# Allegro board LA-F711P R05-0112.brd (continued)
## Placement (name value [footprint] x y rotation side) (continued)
PR404  4.7_0603_5%  [R_0603]  143.05 58.51 90 bottom
PR405  0_0402_5%  [R_0402]  152.73 55.91 90 top
PR414  0_0402_5%  [R0402_0OHM]  149.78 63.98 270 bottom
PR415  0_0402_5%  [R_0402]  134.84 60.73 0 top
PR416  0_0402_5%  [R_0402]  150.67 63.07 90 bottom
PR417  10K_0402_1%  [R_0402]  155.19 63.97 180 bottom
PR418  10K_0402_1%  [R_0402]  155.27 62.86 270 bottom
PR419  10K_0402_1%  [R_0402]  153.36 63.12 90 bottom
PR420  10K_0402_1%  [R_0402]  156.2 61.93 90 bottom
PR425  0_0402_5%  [R_0402]  151.85 55.91 90 top
PR427  200K_0402_1%  [R_0402]  151.62 64.01 270 bottom
PR501  20K_0402_1%  [R_0402]  121.49 8.92 180 bottom
PR502  4.7_0603_5%  [R_0603]  127.18 3.99 90 bottom
PR504  0_0402_5%  [R0402_0OHM]  124.38 8.86 270 top
PR505  1M_0402_1%  [R_0402]  123.36 7.95 90 top
PR506  10K_0402_1%  [R_0402]  119.64 7.78 90 bottom
PR509  1M_0402_1%  [R_0402]  152.89 126.53 270 top
PR510  10.2K_0402_1%  [R_0402]  146.03 126.15 270 top
PR511  0_0402_5%  [R0402_0OHM]  154.68 126.52 180 top
PR512  5.1K_0402_1%  [R_0402]  145.14 127.99 270 top
PR513  0_0402_5%  [R0402_0OHM]  67.99 5.57 90 bottom
PR514  1M_0402_1%  [R_0402]  68.93 6.38 270 bottom
PR515  21.5K_0402_1%  [R_0402]  75.74 7.63 270 bottom
PR516  10.2K_0402_1%  [R_0402]  76.55 5.87 180 bottom
PR517  100K_0402_5%  [R_0402]  118.41 9.04 180 bottom
PR607  0_0402_5%  [R_0402]  165.01 10.18 0 bottom
PR609  0_0402_5%  [R_0402]  165.93 9.32 180 bottom
PR901  0.01_1206_1%  [R_1206_4P-D]  10.38 55.54 0 top
PR909  2_0603_1%  [R_0603]  11.45 53.92 270 top
PR910  2_0603_1%  [R_0603]  12.67 53.91 270 top
PR914  3.3_0603_1%  [R_0603]  13.91 33.78 0 bottom
PR915  4.7_0603_5%  [R_0603]  11.69 31.34 0 bottom
PR916  1_0805_5%~D  [R_0805]  11.79 38.04 90 bottom
PR917  0.005_1206_1%  [R_1206_4P-D]  27.35 4.41 180 top
PR918  100K_0402_1%  [R_0402]  9.95 39.47 270 top
PR919  0_0402_5%  [R_0402]  9.06 39.47 270 bottom
PR920  0_0402_5%  [R0402_0OHM]  9.06 39.47 270 top
PR921  4.7_0603_5%  [R_0603]  10.7 29.43 270 top
PR922  0_0402_5%  [R0402_0OHM]  8.17 39.47 270 bottom
PR923  4.7_1206_5%  [R_1206]  15.63 23.62 180 top
PR924  4.7_1206_5%  [R_1206]  15.53 14.97 180 top
PR925  154K_0402_1%  [R_0402]  7.16 40.79 180 bottom
PR926  0_0402_5%  [R0402_0OHM]  8.17 39.47 270 top
PR927  1M_0402_1%  [R_0402]  7.6 44.67 0 bottom
PR928  0_0402_5%  [R0402_0OHM]  7.29 39.47 270 top
PR929  0_0402_5%  [R0402_0OHM]  8.28 29.43 270 top
PR930  100K_0402_1%  [R_0402]  5.89 40.72 90 top
PR931  100K_0402_1%  [R_0402]  7.16 41.63 270 top
PR932  105K_0402_1%  [R_0402]  4.36 38.68 90 top
PR933  100K_0402_1%  [R_0402]  5.38 39.47 270 top
PR934  0_0402_5%  [R_0402]  6.35 35.4 90 bottom
PR935  0_0402_5%  [R0402_0OHM]  4.49 38.56 90 bottom
PR936  0_0402_5%  [R0402_0OHM]  5.44 33.98 90 top
PR937  1_0603_1%  [R_0603]  7.97 28.57 270 bottom
PR938  1_0603_1%  [R_0603]  6.74 28.56 270 bottom
PR939  0_0402_5%  [R0402_0OHM]  5.51 48.11 270 top
PR940  100_0402_1%  [R_0402]  5.76 31.95 90 bottom
PR941  0_0402_5%  [R0402_0OHM]  6.4 48.11 270 top
PR942  0_0402_5%  [R0402_0OHM]  8.1 45.36 0 top
PR943  0_0603_5%  [R_0603]  13.87 36.54 0 bottom
PR944  442K_0402_1%  [R_0402]  15.37 36.54 180 top
PR945  100K_0402_5%  [R_0402]  10.44 36.41 270 bottom
PR946  0_0402_5%  [R0402_0OHM]  14.61 45.93 0 top
PR947  0_0402_5%  [R0402_0OHM]  5.38 38.56 90 bottom
PR948  10.2K_0402_1%  [R_0402]  5.44 32.99 270 top
PR949  0_0402_5%  [R0402_0OHM]  6.22 33.81 180 bottom
PR950  0_0402_5%  [R_0402]  10 48.92 0 top
PR951  0_0402_5%  [R0402_0OHM]  4.49 41.76 270 top
PR953  100K_0402_1%  [R_0402]  15.63 45.06 270 top
PR960  0_0402_5%  [R0402_0OHM]  9.06 36.52 90 bottom
PR1201  240K_0402_1%  [R_0402]  49.15 101.62 180 bottom
PR1202  300K_0402_5%  [R_0402]  51.35 120.6 90 top
PR1203  1.8M_0402_1%  [R_0402]  46.13 104.74 0 bottom
PR1205  499K_0402_1%  [R_0402]  42.32 113.39 270 top
PR1206  1K_0402_1%  [R_0402]  49.15 105.41 180 bottom
PR1207  499K_0402_1%  [R_0402]  49.58 120.6 90 top
PR1208  102K_0402_1%  [R_0402]  49.15 104.52 180 bottom
PR1209  100K_0402_5%  [R_0402]  70.74 102.35 180 top
PR1210  1M_0402_5%  [R_0402]  60.52 100.82 180 top
PR1211  0_0402_5%  [R0402_0OHM]  60.52 101.83 180 top
PR1212  49.9K_0402_1%  [R_0402]  41.94 111.34 180 top
PR1213  49.9K_0402_1%  [R_0402]  50.54 122.58 180 top
PR1214  100K_0402_5%  [R_0402]  65.87 102.76 90 top
PR1215  0_0402_5%  [R0402_0OHM]  60.5 102.86 180 top
PR1216  0_0402_5%  [R0402_0OHM]  57.3 103.73 180 top
PR1217  84.5K_0402_1%  [R_0402]  48.23 102.51 0 bottom
PR1218  0_0402_5%  [R0402_0OHM]  65.97 105.3 0 top
PR1219  23.2K_0402_1%  [R_0402]  48.31 100.69 270 bottom
PR1220  0_0402_5%  [R0402_0OHM]  57.03 107.76 90 top
PR1221  0_0402_5%  [R_0402]  68.7 107.97 180 top
PR1222  100K_0402_5%  [R_0402]  58.09 108.68 270 top
PR1223  0_0402_5%  [R0402_0OHM]  70.06 104.11 270 top
PR1224  100K_0402_5%  [R_0402]  69.57 107.97 0 top
PR1225  0_0402_5%  [R_0402]  64.91 104.69 270 top
PR1226  100K_0402_5%  [R_0402]  63.29 105.99 90 top
PR1227  100K_0402_5%  [R_0402]  23.54 124.28 90 bottom
PR1228  499K_0402_1%  [R_0402]  26.82 121.48 270 bottom
PR1229  49.9K_0402_1%  [R_0402]  26.27 102.12 90 bottom
PR1230  100K_0402_5%  [R_0402]  70.15 107.04 270 bottom
PR1231  100K_0402_5%  [R_0402]  79.98 113.18 0 bottom
PR1232  100K_0402_5%  [R_0402]  68.83 105.05 180 bottom
PR1233  100K_0402_5%  [R_0402]  82.8 113.44 180 bottom
PR1234  100K_0402_5%  [R_0402]  66.01 109.24 0 bottom
PR1235  100K_0402_5%  [R_0402]  83.69 110.26 180 bottom
PR1236  100K_0402_5%  [R_0402]  29.13 105.38 270 bottom
PR1237  100K_0402_1%  [R_0402]  38.87 99.84 0 bottom
PR1238  0_0402_5%  [R0402_0OHM]  43.84 106.64 180 bottom
PR1239  150K_0402_1%  [R_0402]  41.58 98.63 90 bottom
PR1240  100K_0402_1%  [R_0402]  39.39 106.8 270 bottom
PR1241  0_0402_5%  [R0402_0OHM]  71.12 108.99 180 bottom
PR1242  0_0402_5%  [R0402_0OHM]  87.88 113.31 180 bottom
PR1243  0_0402_5%  [R0402_0OHM]  40.42 106.8 270 bottom
PR1244  0_0402_5%  [R0402_0OHM]  63.29 107.01 90 bottom
PR1245  0_0402_5%  [R0402_0OHM]  76.5 112.22 90 bottom
PR1246  100K_0402_1%  [R_0402]  43.48 99.54 270 bottom
PR1247  100K_0402_1%  [R_0402]  39.78 101.69 180 bottom
PR1248  0_0402_5%  [R_0402]  47.4 97.47 90 bottom
PR1249  10K_0402_5%  [R_0402]  49.25 97.47 90 bottom
PR1250  0_0402_5%  [R0402_0OHM]  48.29 97.47 90 bottom
PR1251  300K_0402_5%  [R_0402]  40.43 105.1 90 top
PR1252  100K_0402_5%  [R_0402]  40.43 107.01 90 top
PR1253  100K_0402_5%  [R_0402]  64.75 102.79 270 top
PR1254  0_0402_5%  [R_0402]  61.48 105.85 0 top
PR1255  150K_0402_1%  [R_0402]  28.24 121.39 270 top
PR1257  0_0402_5%  [R0402_0OHM]  85.59 110.26 180 bottom
PR1258  0_0402_5%  [R_0402]  71.12 108.1 180 bottom
PR1259  100K_0402_5%  [R_0402]  65.02 105.18 0 bottom
PR1260  0_0402_5%  [R_0402]  62.33 109.24 0 bottom
PR1261  0_0402_5%  [R_0402]  64.11 109.24 0 bottom
PR1262  100K_0402_5%  [R_0402]  58.14 103.73 0 top
PR1700  100_0402_1%  [R_0402]  109.81 84.37 0 bottom
PR1701  12K_0402_1%  [R_0402]  63.95 80.59 180 top
PR1702  7.5K_0603_1%  [R_0603]  65.95 84.45 0 bottom
PR1703  10_0402_1%  [R_0402]  65.7 82.34 180 top
PR1704  499_0402_1%  [R_0402]  65.13 76.58 180 top
PR1705  100_0402_1%  [R_0402]  64.78 77.95 0 top
PR1706  45.3_0402_1%  [R_0402]  65.7 78.82 180 top
PR1707  45.3_0402_1%  [R_0402]  65.69 79.71 180 top
PR1708  0_0402_5%  [R0402_0OHM]  65.68 85.01 180 top
PR1709  1K_0402_1%  [R_0402]  63.92 85.87 180 top
PR1710  0_0402_5%  [R0402_0OHM]  65.68 85.88 90 top
PR1711  1.74K_0402_1%  [R_0402]  63.93 87.65 270 top
PR1712  100_0402_1%  [R_0402]  60.91 77.37 0 top
PR1713  28K_0402_1%  [R_0402]  60.12 82.69 0 bottom
PR1714  100_0402_1%  [R_0402]  112.49 84.37 180 bottom
PR1715  49.9_0402_1%  [R_0402]  62.64 79.7 0 top
PR1716  10K_0402_1%  [R_0402]  63.93 81.91 180 bottom
PR1717  0_0402_5%  [R0402_0OHM]  63.56 78.81 180 top
PR1718  12K_0402_1%  [R_0402]  60.68 85.37 0 bottom
PR1719  10_0402_1%  [R_0402]  62.64 77.93 0 top
PR1720  1.5K_0402_1%  [R_0402]  67.28 83.24 180 top
PR1721  100_0402_1%  [R_0402]  103.45 84.98 270 bottom
PR1722  38.3K +-1% 0402  [R_0402]  61.03 80.92 180 bottom
PR1723  0_0402_5%  [R0402_0OHM]  61.86 89.26 270 bottom
PR1724  0_0402_5%  [R0402_0OHM]  63.01 81 0 bottom
PR1725  100_0402_1%  [R_0402]  98.13 82.94 180 bottom
PR1726  0_0402_5%  [R0402_0OHM]  61.27 90.99 270 top
PR1727  1.78K_0402_1%  [R_0402]  61.28 89.26 270 top
PR1728  0_0402_5%  [R0402_0OHM]  60.98 76.5 0 top
PR1729  100_0402_1%  [R_0402]  103.53 82.89 180 bottom
PR1730  2.05K_0402_1%  [R_0402]  61.01 74.72 0 top
PR1731  49.9_0402_1%  [R_0402]  59.51 89.25 90 top
PR1732  26.1K_0402_1%  [R_0402]  58.01 84.56 90 bottom
PR1733  30.1K_0402_1%  [R_0402]  57.72 78.68 90 bottom
PR1734  1K_0402_1%  [R_0402]  59.47 88.39 0 top
PR1735  0_0402_5%  [R0402_0OHM]  62.78 74.75 270 top
PR1736  100_0402_1%  [R_0402]  99.03 82.92 90 bottom
PR1737  3.65K_0402_1%  [R_0402]  57.76 89.23 90 top
PR1738  49.9_0402_1%  [R_0402]  59.53 73.06 270 top
PR1739  1K_0402_1%  [R_0402]  58.64 73.93 0 top
PR1740  3.65K_0402_1%  [R_0402]  57.77 73.08 270 top
PR1741  30.1K_0402_1%  [R_0402]  56.87 89.28 270 top
PR1742  13K_0402_1%  [R_0402]  56.03 76.94 270 top
PR1743  75K_0402_1%  [R_0402]  56.01 90.14 180 top
PR1744  75K_0402_1%  [R_0402]  56.04 74.02 180 top
PR1745  1K_0402_1%  [R_0402]  54.28 77.83 90 bottom
PR1746  165K_0402_1%  [R_0402]  55.15 91.55 0 top
PR1747  113K_0603_1%  [R_0603]  58.4 91.97 180 top
PR1748  165K_0402_1%  [R_0402]  54.28 74.04 90 top
PR1749  76.8K_0603_1%  [R_0603]  53.11 73.23 270 top
PR1750  113K_0603_1%  [R_0603]  58.4 93.24 180 top
PR1751  113K_0603_1%  [R_0603]  58.4 94.51 180 top
PR1752  113K_0603_1%  [R_0603]  58.4 95.78 180 top
PR1753  1K_0402_1%  [R_0402]  51.08 85.24 0 top
PR1754  2.2_0603_5%  [R_0603]  50.57 82.42 0 top
PR1755  11.8K_0402_1%  [R_0402]  54.24 79.61 0 bottom
PR1756  25.5K_0402_1%  [R_0402]  54.3 81.33 0 bottom
PR1757  7.68K_0402_1%  [R_0402]  58.16 91.34 180 bottom
PR1758  102K +-1% 0402  [R_0402]  53.67 83.11 0 bottom
PR1759  4.3K +-1% 0402  [R_0402]  53.67 82.22 0 bottom
PR1760  24.9K_0402_1%  [R_0402]  51.54 81.35 180 top
PR1761  97.6K_0402_1%  [R_0402]  51.54 80.08 180 top
PR1762  97.6K_0402_1%  [R_0402]  51.54 79.19 180 top
PR1763  7.68K_0402_1%  [R_0402]  51.99 72.92 270 top
PR1764  7.68K_0402_1%  [R_0402]  58.16 92.35 180 bottom
PR1765  7.68K_0402_1%  [R_0402]  58.16 93.37 180 bottom
PR1766  7.68K_0402_1%  [R_0402]  58.16 94.39 180 bottom
PR1767  0_0402_5%  [R0402_0OHM]  77.27 94.63 90 top
PR1768  0_0402_5%  [R0402_0OHM]  50.59 69.32 270 bottom
PR1769  8.66K +-1% 0402  [R_0402]  77.27 96.38 90 top
PR1770  8.66K +-1% 0402  [R_0402]  48.81 68.4 90 bottom
PR1771  2.21K +-1% 0402  [R_0402]  63.95 88.54 180 top
PR1772  1K_0402_1%  [R_0402]  54.91 86.05 90 bottom
PR1773  1K_0402_1%  [R_0402]  53.89 86.05 90 bottom
PR1774  1K_0402_1%  [R_0402]  52.88 86.05 90 bottom
PR1775  1K_0402_1%  [R_0402]  51.86 86.05 90 bottom
PR1776  1K_0402_1%  [R_0402]  53.34 76.1 180 top
PR1800  2_0603_5%  [R_0603]  65.87 98.17 90 top
PR1801  3.9_0603_1%  [R_0603]  70.29 101.69 90 bottom
PR1802  10_0402_1%  [R_0402]  76.88 89.08 90 top
PR1803  1_1206_5%  [R_1206]  73.71 91.85 180 top
PR1804  2_0603_5%  [R_0603]  77.16 100.56 90 top
PR1805  3.9_0603_1%  [R_0603]  79.18 102.43 90 top
PR1806  10_0402_1%  [R_0402]  87.25 92.99 180 top
PR1807  1_1206_5%  [R_1206]  80.77 93.19 90 top
PR1900  2_0603_5%  [R_0603]  85.9 94.08 90 top
PR1901  3.9_0603_1%  [R_0603]  86.05 98.74 180 top
PR1902  10_0402_1%  [R_0402]  91.91 89.05 90 top
PR1903  1_1206_5%  [R_1206]  89.89 93.52 0 top
PR1904  2_0603_5%  [R_0603]  96.16 96.16 180 top
PR1905  3.9_0603_1%  [R_0603]  94.22 99 0 top
PR1906  10_0402_1%  [R_0402]  97.72 89.07 90 top
PR1907  1_1206_5%  [R_1206]  98.32 94.54 180 top
PR2000  2_0603_5%  [R_0603]  43.84 60.33 180 bottom
PR2001  3.9_0603_1%  [R_0603]  42.29 65.14 180 bottom
PR2002  10_0402_1%  [R_0402]  55.11 68.34 180 bottom
PR2003  1_1206_5%  [R_1206]  50.03 59.01 180 bottom
PR2004  2_0603_5%  [R_0603]  104.15 87.03 90 bottom
PR2005  3.9_0603_1%  [R_0603]  104.4 91.89 180 bottom
PR2006  1_1206_5%  [R_1206]  115.61 96.6 180 bottom
PR2007  1K_0402_1%  [R_0402]  50.97 86.07 90 bottom
PR2008  1K_0402_1%  [R_0402]  167 9.65 0 bottom
PR2009  0_0402_5%  [R_0402]  150.02 58.06 0 top
PR2010  0_0402_5%  [R_0402]  154.68 125.63 180 top
PR2011  0_0402_5%  [R_0402]  160.13 8.33 90 bottom
PR2012  0_0402_5%  [R_0402]  161.02 8.33 90 bottom
PR2013  100K_0402_5%  [R_0402]  161.91 9.25 270 bottom
PRP1  100_0804_8P4R_5%  [RP_0804_8P4R]  7.09 12.59 0 top
PT1  PAD~D  [TPC12]  47.29 99.3 180 bottom
PU1  MC74VHC1G08DFT2G SC70 5P AND  [TC7SH08FU_SSOP5]  75.29 116.14 90 top
PU2  AP2204R-3.3TRG1_SOT89-3  [AP2204R-3P3TRG1_SOT89-3]  71.42 113.54 270 bottom
PU100  -  [SY8288BRAC_QFN20_3X3]  88.91 5.61 90 bottom
PU102  -  [SY8288CRAC_QFN20_3X3]  125.37 131.34 180 top
PU200  -  [SY8210AQVC_QFN19_4X3]  44.71 8.83 270 bottom
PU301  -  [SY8286RAC_QFN20_3X3]  169.15 4.9 90 bottom
PU401  -  [SY8057BQDC_QFN16_3X3]  149.93 59.03 0 bottom
PU501  -  [RT8097ALGE_SOT23-6]  122.6 6.49 270 bottom
PU502  -  [EM1109V-AD_DFN3308-8_3X3]  147.43 127.94 270 top
PU503  -  [EM1109V-AD_DFN3308-8_3X3]  74.25 7.75 270 bottom
PU901  ISL9538HRTZTS277_TQFN32_4X4~D  [ISL9538HRTZTS277_TQFN32_4X4]  8.41 31.71 90 top
PU903  MC74VHC1G08DFT2G SC70 5P AND  [TC7SH08FU_SSOP5]  11.53 47.3 270 top
PU1200  MC74VHC1G08DFT2G SC70 5P AND  [TC7SH08FU_SSOP5]  58.57 101.44 90 top
PU1201  -  [LM393DGKR_VSSOP8]  46.38 103.09 180 bottom
PU1700  NCP81215DPA0MNTXG_QFN52_6X6  [NCP81215MNTXG_QFN52_6X6]  59.73 85.47 270 top
PU1800  -  [NCP302045MNTXG_PQFN33_5X5]  68.21 100.47 0 bottom
PU1801  -  [NCP302045MNTXG_PQFN33_5X5]  77.68 100.65 0 bottom
PU1900  NCP302045MN_PQFN33_5X5  [NCP302045MNTXG_PQFN33_5X5]  86.12 96.67 90 bottom
PU1901  NCP302045MN_PQFN33_5X5  [NCP302045MNTXG_PQFN33_5X5]  95.76 96.78 90 bottom
PU2000  NCP302045MN_PQFN33_5X5  [NCP302045MNTXG_PQFN33_5X5]  43.55 62.7 90 bottom
PU2001  NCP302045MN_PQFN33_5X5  [NCP302045MNTXG_PQFN33_5X5]  105.77 89.47 90 bottom
QE2  -  [DMN65D8LDW-7_SOT363-6]  303.18 45.05 0 top
QE3  LMBT3904WT1G SC70-3  [MMBT3904WT1G_SC70-3]  94.13 67.02 180 top
QE4  LMBT3904WT1G SC70-3  [MMBT3904WT1G_SC70-3]  323.12 14.31 90 top
QE5  LMBT3904WT1G SC70-3  [MMBT3904WT1G_SC70-3]  11.48 104.6 90 bottom
QE6  LMBT3904WT1G SC70-3  [MMBT3904WT1G_SC70-3]  99.73 102.28 180 bottom
QE7  LMBT3904WT1G SC70-3  [MMBT3904WT1G_SC70-3]  78.31 10.83 90 bottom
QE11  -  [L2N7002WT1G_SC-70-3]  324.39 17.11 270 top
QE12  -  [L2N7002WT1G_SC-70-3]  318.84 49.55 0 top
QE15  -  [LP2301ALT1G_SOT23-3]  310.94 53.87 0 top
QE17  -  [L2N7002WT1G_SC-70-3]  314.84 51.48 180 top
QH4  -  [DMN65D8LDW-7_SOT363-6]  218.24 9.33 90 top
QH6  -  [L2N7002WT1G_SC-70-3]  196.82 6.12 270 bottom
QH7  -  [LP2301ALT1G_SOT23-3]  202.28 7.92 0 bottom
QL1  -  [DMN65D8LDW-7_SOT363-6]  310.29 87.34 0 top
QL2  -  [DMN65D8LDW-7_SOT363-6]  311.81 92.04 90 top
QN1  -  [DMN65D8LDW-7_SOT363-6]  268.89 16.6 180 bottom
QN6  -  [L2N7002WT1G_SC-70-3]  268.57 10.32 0 top
QR1  -  [L2N7002WT1G_SC-70-3]  37.44 71.47 90 bottom
QT1  -  [DMN66D0LDW-7_SOT363-6]  18.7 83.02 0 top
QV1  -  [AO6405_TSOP6]  123.22 113.76 0 top
QV2  -  [L2N7002WT1G_SC-70-3]  124.62 109.18 90 top
QV3  -  [DMN65D8LDW-7_SOT363-6]  115.05 124.75 270 top
QV4  -  [L2N7002WT1G_SC-70-3]  97.9 122.2 270 top
QV5  -  [L2N7002WT1G_SC-70-3]  119.43 125.31 0 top
QV7  -  [L2N7002WT1G_SC-70-3]  127.22 96.48 90 top
QV8  -  [LP2301ALT1G_SOT23-3]  127.92 102.35 180 top
QV18  -  [MMBT3906H_SOT23-3]  147.36 95.6 180 bottom
QV19  MMBT3904WT1G SC70-3  [MMBT3904WT1G_SC70-3]  152.9 96.56 270 bottom
QV20  -  [MMBT3906H_SOT23-3]  150.68 91.78 180 bottom
QV21  MMBT3904WT1G SC70-3  [MMBT3904WT1G_SC70-3]  157.71 93.05 270 bottom
QZ1  -  [LP2301ALT1G_SOT23-3]  121.16 99.91 90 bottom
QZ2  -  [DMN65D8LDW-7_SOT363-6]  307.26 60.48 0 bottom
QZ3  -  [DDTA144VCA-7-F_SOT23-3]  304.34 58.57 180 bottom
QZ4  -  [L2N7002WT1G_SC-70-3]  301.29 48.41 0 top
QZ7  -  [DMN65D8LDW-7_SOT363-6]  351.64 112.05 270 bottom
QZ15  -  [BSS138W-7-F_SOT323-3]  283.26 2.82 90 top
QZ16  -  [LP2301ALT1G_SOT23-3]  277.4 3 270 top
QZ17  -  [DMN65D8LDW-7_SOT363-6]  297.82 44.51 270 bottom
QZ18  -  [DMN65D8LDW-7_SOT363-6]  291.65 43.96 0 bottom
R274  0_0603_5%  [R0603_0OHM]  16.8 61.44 180 top
RA3  0_0603_5%  [R_0603]  337.47 44.94 90 top
RA5  2.2K_0402_5%  [R_0402]  345.95 35.99 0 bottom
RA6  2.2K_0402_5%  [R_0402]  345.95 37.9 0 bottom
RA7  16.2_0402_1%  [R_0402]  349.26 42.53 0 top
RA8  16.2_0402_1%  [R_0402]  349.22 41.55 0 top
RA9  33_0402_5%  [R_0402]  342.4 30.46 90 top
RA12  1K_0402_5%  [R_0402]  346.2 33.43 180 bottom
RA13  1K_0402_5%  [R_0402]  351.39 38.18 45 top
RA14  22_0402_5%  [R_0402]  340.18 30.46 90 top
RA17  33_0402_5%  [R_0402]  341.32 31.37 270 top
RA18  10K_0402_5%  [R_0402]  337.23 27.28 270 top
RA35  0_0402_5%  [R_0402]  338.34 38.99 270 bottom
RA36  0_0402_5%  [R_0402]  366.98 37.89 90 top
RA37  0_0402_5%  [R_0402]  360.22 23.6 270 top
RA44  100K_0402_5%  [R_0402]  342.85 43.73 90 bottom
RA45  10K_0402_5%  [R_0402]  352.02 37.55 45 top
RA48  0_0402_5%  [R_0402]  335.89 29.87 0 top
RA50  0_0402_5%  [R_0402]  336.34 26.36 90 top
RA51  10K_0402_5%  [R_0402]  353.93 35.64 45 top
RA52  100K_0402_5%  [R_0402]  339.23 30.46 90 top
RA53  0_0402_5%  [R_0402]  350.69 39.14 45 top
RA54  0_0402_5%  [R_0402]  349.93 39.78 45 top
RA57  4.7K_0402_5%  [R_0402]  341.45 43.79 90 top
RA58  4.7K_0402_5%  [R_0402]  342.47 43.79 90 top
RA59  100K_0402_1%  [R_0402]  345.28 32.16 0 top
RA60  200K_0402_1%  [R_0402]  347.19 32.16 0 top
RA61  100K_0402_5%  [R_0402]  345.28 33.17 0 top
RC1  24.9_0402_1%  [R_0402]  120.37 83.59 0 top
RC2  24.9_0402_1%  [R_0402]  122.81 47.01 180 top
RC5  121_0402_1%  [R_0402]  122.81 46.13 180 top
RC6  75_0402_1%  [R_0402]  121.66 47.9 180 top
RC7  100_0402_1%  [R_0402]  121.66 48.79 180 top
RC66  20_0402_5%  [R_0402]  125 87.72 0 bottom
RC71  1K_0402_5%  [R_0402]  138.21 57.49 0 top
RC74  10K_0402_5%  [R_0402]  223.91 36.73 0 bottom
RC75  10K_0402_5%  [R_0402]  219.55 17.28 270 top
RC78  60.4_0402_1%  [R_0402]  139.09 56.61 180 top
RC79  49.9_0402_1%  [R_0402]  71.88 72.1 0 bottom
RC80  1K_0402_5%  [R_0402]  122.84 86.07 180 top
RC83  1K_0402_5%  [R_0402]  71.88 73.09 0 bottom
RC84  499_0402_1%  [R_0402]  73.67 72.57 0 bottom
RC114  49.9_0402_1%  [R_0402]  74.93 66.57 180 bottom
RC115  2.2K_0402_5%  [R_0402]  41.94 48.15 90 top
RC121  1K_0402_5%  [R_0402]  36.61 35.96 90 top
RC122  0_0402_5%  [R_0402]  32.67 36.87 270 top
RC124  1K_0402_5%  [R_0402]  38.91 35.51 90 top
RC126  1K_0402_5%  [R_0402]  43.74 35.58 90 top
RC127  1K_0402_5%  [R_0402]  51.67 54.25 90 top
RC128  1K_0402_5%  [R_0402]  229.54 12.98 0 bottom
RC129  0_0402_5%  [R_0402]  55.11 45.62 180 top
RC132  150_0402_5%  [R_0402]  54.91 48.87 270 top
RC133  1.5K_0402_5%  [R_0402]  55.11 46.51 180 top
RC135  51_0402_5%  [R_0402]  46.51 48.1 90 top
RC136  51_0402_5%  [R_0402]  48.56 48.16 90 top
RC137  3K_0402_5%  [R_0402]  43.84 48.15 90 top
RC138  51_0402_5%  [R_0402]  33.68 35.96 90 top
RC139  51_0402_5%  [R_0402]  74.93 69.75 180 bottom
RC140  100_0402_1%  [R_0402]  100.75 84.72 270 bottom
RC141  100_0402_1%  [R_0402]  100.85 82.96 180 bottom
RC143  0_0402_5%  [R_0402]  73.02 69.87 180 bottom
RC144  0_0402_5%  [R_0402]  42.83 48.15 90 top
RC152  56.2_0402_1%  [R_0402]  69.36 85.93 0 top
RC153  220_0402_5%  [R_0402]  71.18 85.94 0 top
RC157  100_0402_5%  [R_0402]  69.34 85.04 0 top
RC166  1K_0402_5%  [R_0402]  71.04 70.84 270 bottom
RC168  20_0402_5%  [R_0402]  73.86 73.8 90 bottom
RC169  0_0402_5%  [R_0402]  120.17 85.56 270 top
RC171  0_0402_5%  [R_0402]  77.25 48.04 180 top
RC177  30_0402_5%  [R_0402]  115.02 68.29 0 top
RC178  0_0402_5%  [R_0402]  132.18 76.91 0 top
RC179  0_0402_5%  [R_0402]  124.06 83.98 90 top
RC181  1K_0402_5%  [R_0402]  75 69.99 180 top
RC216  0_0603_1%  [R0603_0OHM]  38.64 48.22 0 top
RC217  0_0402_5%  [R_0402]  53.89 48.87 270 top
RC218  150_0402_5%  [R_0402]  53.89 51.28 270 top
RC219  10K_0402_5%  [R_0402]  54.91 51.28 270 top
RC221  49.9_0402_1%  [R_0402]  101.71 82.99 90 bottom
RC228  0_0402_5%  [R_0402]  50.59 48.16 90 top
RC229  0_0402_5%  [R_0402]  49.58 48.16 90 top
RC230  0_0402_5%  [R_0402]  47.4 48.1 90 top
RC239  0_0402_5%  [R_0402]  74.93 68.6 180 bottom
RC240  0_0402_5%  [R_0402]  74.93 67.59 180 bottom
RC241  1.5K_0402_5%  [R_0402]  52.75 51.28 270 top
RC304  0_0402_5%  [R_0402]  129.66 70 180 top
RC314  0_0402_5%  [R_0402]  75.02 70.88 180 top
RC315  0_0402_5%  [R_0402]  73.02 71.14 180 bottom
RC319  0_0402_5%  [R_0402]  70.65 73.94 90 bottom
RC321  1K_0402_5%  [R_0402]  75.35 69.11 180 top
RC322  1K_0402_5%  [R_0402]  75.24 64.28 180 top
RC323  1K_0402_5%  [R_0402]  77.11 63.63 180 top
RC324  1K_0402_5%  [R_0402]  75.24 65.3 180 top
RC325  1K_0402_5%  [R_0402]  75.24 66.31 180 top
RC326  0_0402_5%  [R_0402]  127.14 73.13 0 top
RC366  15_0402_5%  [R_0402]  228.49 26.53 90 bottom
RC367  15_0402_5%  [R_0402]  226.73 26.54 90 bottom
RC368  15_0402_5%  [R_0402]  225.84 26.54 90 bottom
RC369  15_0402_5%  [R_0402]  227.62 26.53 90 bottom
RC370  10K_0402_5%  [R_0402]  214.64 32.86 0 top
RC436  1K_0402_5%  [R_0402]  75.04 71.75 180 top
RC437  1K_0402_5%  [R_0402]  75.3 68.1 180 top
RC438  1K_0402_5%  [R_0402]  75.58 65.05 270 bottom
RC439  1K_0402_5%  [R_0402]  74.68 65.05 270 bottom
RC440  1K_0402_5%  [R_0402]  75.32 67.21 180 top
RC441  1K_0402_5%  [R_0402]  72.06 67.02 0 bottom
RC442  1K_0402_5%  [R_0402]  77.11 62.76 180 top
RC443  1K_0402_5%  [R_0402]  77.12 64.52 180 top
RC557  100K_0402_5%  [R_0402]  223.76 33.57 270 bottom
RC558  100K_0402_5%  [R_0402]  224.65 34.33 270 bottom
RC560  0_0402_5%  [R_0402]  219.38 29.84 90 top
RC561  0_0402_5%  [R_0402]  218.51 29.84 90 top
RD4  0_0402_5%  [R_0402]  95.98 13.87 0 top
RD5  0_0402_5%  [R_0402]  96.9 14.76 180 top
RD6  0_0402_5%  [R_0402]  98.68 13.87 180 top
RD7  0_0402_5%  [R_0402]  97.76 14.76 0 top
RD8  0_0402_5%  [R_0402]  73 14.62 180 top
RD9  0_0402_5%  [R_0402]  72.09 13.68 0 top
RD10  0_0603_5%  [R_0603]  91.61 22.95 270 top
RD11  470_0402_1%  [R_0402]  53.12 13.65 90 top
RD12  0_0402_5%  [R_0402]  54 13.65 90 top
RD14  1K_0402_5%  [R_0402]  61.62 14.57 270 top
RD15  1K_0402_1%  [R_0402]  68.13 12.16 0 top
RD16  1K_0402_1%  [R_0402]  69.04 11.24 180 top
RD17  2_0402_1%  [R_0402]  69.12 13.65 90 top
RD18  24.9_0402_1%  [R_0402]  67.34 13.65 90 top
RD19  330K_0402_5%  [R_0402]  154.82 13.58 90 top
RD20  0_0402_5%  [R_0402]  176.68 16.15 0 top
RD21  0_0402_5%  [R_0402]  178.96 16.03 0 top
RD22  0_0402_5%  [R_0402]  176.68 17.04 0 top
RD23  0_0402_5%  [R_0402]  178.96 16.92 0 top
RD24  0_0402_5%  [R_0402]  153.83 13.68 180 top
RD25  0_0402_5%  [R_0402]  152.94 14.57 0 top
RD26  0_0603_5%  [R_0603]  173.38 26.13 0 top
RD27  1K_0402_5%  [R_0402]  142.14 14.57 270 top
RD28  1K_0402_1%  [R_0402]  149.38 13.68 90 top
RD29  1K_0402_1%  [R_0402]  150.27 14.57 270 top
RD30  2_0402_1%  [R_0402]  148.38 14.45 270 top
RD31  24.9_0402_1%  [R_0402]  147.37 15.26 90 top
RE5  10K_0402_5%  [R_0402]  325.98 40.66 0 top
RE8  100K_0402_5%  [R_0402]  325.72 33.93 0 top
RE10  100K_0402_5%  [R_0402]  326.88 39.08 0 bottom
RE11  100K_0402_5%  [R_0402]  308.86 43.71 180 top
RE12  100K_0402_5%  [R_0402]  323.13 43.84 0 bottom
RE20  100K_0402_5%  [R_0402]  310.02 29.08 180 top
RE21  10K_0402_5%  [R_0402]  325.04 42.7 180 bottom
RE25  100K_0402_5%  [R_0402]  321.18 27.08 180 top
RE26  10_0402_5%  [R_0402]  322.63 24.59 90 top
RE30  0_0402_5%  [R_0402]  332.6 11.79 270 bottom
RE31  100K_0402_5%  [R_0402]  313.72 47.97 0 top
RE32  0_0402_5%  [R_0402]  313.99 42.49 90 bottom
RE33  1K_0402_5%  [R_0402]  314.61 48.99 180 top
RE35  10K_0402_5%  [R_0402]  323.64 28.42 270 top
RE37  2.2K_0402_5%  [R_0402]  310.64 25.55 180 top
RE38  10K_0402_5%  [R_0402]  329.51 33.67 0 top
RE43  2.2K_0402_5%  [R_0402]  310.64 27.08 180 top
RE48  10K_0402_5%  [R_0402]  203.61 66.51 90 top
RE51  10K_0402_5%  [R_0402]  204.49 66.51 90 top
RE55  100K_0402_5%  [R_0402]  309.55 44.78 90 top
RE56  10K_0402_5%  [R_0402]  311.7 41.99 90 bottom
RE57  1K_0402_5%  [R_0402]  307.77 44.78 90 top
RE58  100K_0402_5%  [R_0402]  308.66 44.78 90 top
RE59  0_0402_5%  [R_0402]  326.64 34.82 180 bottom
RE60  33_0402_5%  [R_0402]  325.73 34.82 0 top
RE63  100K_0402_5%  [R_0402]  328.83 39.71 270 top
RE64  300_0402_5%  [R_0402]  313.43 36.22 180 bottom
RE65  100_0402_1%  [R_0402]  326.69 39.73 270 top
RE67  10K_0402_5%  [R_0402]  304.45 43.91 270 top
RE68  100K_0402_5%  [R_0402]  303.18 48.22 90 top
RE69  8.2K_0402_5%  [R_0402]  324.4 15.21 270 top
RE70  2.2K_0402_5%  [R_0402]  321.09 16.35 180 top
RE71  10_0402_1%  [R_0402]  330.83 12.72 180 bottom
RE72  10K_0402_5%  [R_0402]  331.69 12.72 0 bottom
RE73  10K_0402_5%  [R_0402]  326.42 13.3 0 bottom
RE74  10K_0402_5%  [R_0402]  331.71 11.79 270 bottom
RE75  100K_0402_5%  [R_0402]  326.42 12.16 0 bottom
RE77  1.58K_0402_1%  [R_0402]  321.1 41.83 90 bottom
RE79  62K_0402_5%  [R_0402]  328.96 35.31 180 top
RE83  100K_0402_5%  [R_0402]  328.04 36.2 0 top
RE84  100K_0402_5%  [R_0402]  325.73 36.6 0 bottom
RE85  100K_0402_5%  [R_0402]  325.73 35.71 0 bottom
RE86  10K_0402_5%  [R_0402]  324.93 11.07 180 bottom
RE90  0_0402_5%  [R_0402]  320.2 17.24 0 top
RE91  100K_0402_5%  [R_0402]  323.76 37.44 90 bottom
RE92  100K_0402_5%  [R_0402]  317.55 42.49 90 bottom
RE93  100K_0201_5%  [R_0201]  318.87 46.72 0 top
RE94  75_0402_5%  [R_0402]  319.68 50.82 180 top
RE95  100K_0402_5%  [R_0402]  318.18 27.38 90 top
RE100  0_0201_5%  [R_0201]  321.86 29.96 90 bottom
RE101  0_0201_5%  [R_0201]  321.29 29.96 90 bottom
RE274  0_0402_5%  [R_0402]  309.6 30.38 0 top
RE275  0_0402_5%  [R_0402]  324.4 24.71 90 top
RE280  0_0402_5%  [R_0402]  339.81 49.31 270 top
RE288  100_0402_5%  [R_0402]  325.79 36.9 0 top
RE290  0_0402_5%  [R_0402]  314.58 42.7 180 top
RE292  0_0402_5%  [R_0402]  338.24 47.4 180 top
RE300  8.2K_0402_5%  [R_0402]  326.64 33.93 180 bottom
RE301  10K_0402_5%  [R_0402]  323.73 45.07 90 top
RE302  2.2K_0402_5%  [R_0402]  317.29 42.75 90 top
RE303  2.2K_0402_5%  [R_0402]  315.77 42.62 90 top
RE304  0_0402_5%  [R_0402]  342.55 48.1 180 top
RE306  0_0402_5%  [R_0402]  324.01 12.79 0 bottom
RE308  0_0402_5%  [R_0402]  323.47 30.5 180 bottom
RE312  300_0402_5%  [R_0402]  311.45 33.35 90 bottom
RE313  10K_0402_5%  [R_0402]  313.31 34.31 180 bottom
RE314  100_0402_1%  [R_0402]  309.15 38.32 270 top
RE318  0_0402_5%  [R_0402]  311.53 36.22 180 top
RE324  100K_0402_5%  [R_0402]  315.77 42.49 90 bottom
RE340  10K_0402_5%  [R_0402]  313.79 27.33 0 bottom
RE342  10K_0402_5%  [R_0402]  308.53 35.2 0 top
RE343  240K_0402_5%  [R_0402]  308.66 40.23 270 top
RE349  43K_0402_1%  [R_0402]  313.99 26.49 90 top
RE350  33_0402_5%  [R_0402]  318.26 35.2 180 bottom
RE362  100K_0402_5%  [R_0402]  308.86 42.82 180 top
RE365  100K_0402_5%  [R_0402]  325.98 41.55 0 top
RE375  0_0402_5%  [R_0402]  268.78 20.81 0 bottom
RE505  100K_0402_5%  [R_0402]  306.64 47.69 0 top
RE507  100K_0402_5%  [R_0402]  316.66 42.49 90 bottom
RE508  100K_0402_5%  [R_0402]  314.88 42.49 90 bottom
RE525  0_0402_5%  [R_0402]  319.66 52.79 270 top
RE526  10K_0402_5%  [R_0402]  325.88 40.72 180 bottom
RE532  4.7K_0402_5%  [R_0402]  319.35 24.42 180 bottom
RE536  0_0402_5%  [R_0402]  317.46 52.36 270 top
RE539  100_0402_5%  [R_0402]  329.75 39.71 270 top
RE541  100K_0402_5%  [R_0402]  314.31 54.46 90 top
RE543  1M_0402_5%  [R_0402]  317.85 53.83 90 top
RE546  10K_0402_5%  [R_0402]  312.76 53.1 270 top
RE547  100K_0402_5%  [R_0402]  315.85 24.6 270 top
RE548  0_0402_5%  [R_0402]  312.17 41.1 180 bottom
RE549  100K_0402_5%  [R_0402]  307.31 30.03 270 top
RE550  100K_0402_5%  [R_0402]  308.26 30.07 270 top
RE551  0_0402_5%  [R_0402]  308.48 56.35 90 top
RE552  0_0402_5%  [R_0402]  323.49 29.61 180 bottom
RE560  0_0402_5%  [R_0402]  268.78 19.94 0 bottom
RE561  100K_0402_5%  [R_0402]  313.09 27.39 270 top
RE562  0_0201_5%  [R_0201]  320.72 29.96 90 bottom
RE565  0_0402_5%  [R_0402]  318.73 54.75 270 top
RE566  0_0402_5%  [R_0402]  307.37 41.62 0 top
RE702  1M_0402_5%  [R_0402]  308.16 22.5 180 top
RE703  0_0402_5%  [R_0402]  323.58 22.16 90 top
RH1  100K_0402_5%  [R_0402]  210.47 47.73 270 top
RH10  0_0402_5%  [R_0402]  225.79 26.53 0 top
RH11  0_0402_5%  [R_0402]  223.85 25.64 270 top
RH13  0_0402_5%  [R_0402]  225.79 27.42 0 top
RH14  0_0402_5%  [R_0402]  226.31 29.35 0 top
RH15  0_0402_5%  [R_0402]  226.93 34.51 90 top
RH28  33_0402_5%  [R_0402]  240.79 4.72 180 bottom
RH29  33_0402_5%  [R_0402]  225.53 18.16 180 bottom
RH30  20K_0402_5%  [R_0402]  238.76 17.35 90 bottom
RH37  0_0402_5%  [R_0402]  236.89 19.89 180 bottom
RH38  30_0402_5%  [R_0402]  210.65 51.96 270 bottom
RH39  30_0402_5%  [R_0402]  209.69 51.35 270 bottom
RH42  30_0402_5%  [R_0402]  208.68 50.43 90 bottom
RH43  0_0402_5%  [R_0402]  215.93 13.97 90 bottom
RH44  10M_0402_5%  [R_0402]  216.84 14.79 0 bottom
RH45  33_0402_5%  [R_0402]  221.34 40.93 180 bottom
RH46  33_0402_5%  [R_0402]  221.35 41.8 180 bottom
RH48  33_0402_5%  [R_0402]  221.34 39.15 180 bottom
RH50  33_0402_5%  [R_0402]  222.17 43.42 180 bottom
RH56  1K_0402_5%  [R_0402]  227.2 30.26 180 bottom
RH57  1K_0402_5%  [R_0402]  227.18 31.14 180 bottom
RH60  0_0402_5%  [R_0402]  238.6 25.79 0 bottom
RH61  4.7K_0201_5%  [R_0201]  226.46 31.97 180 bottom
RH62  0_0402_5%  [R_0402]  234.3 25.04 90 bottom
RH65  100K_0402_5%  [R_0402]  238.6 27.7 0 bottom
RH66  0_0402_5%  [R0402_0OHM]  215.48 48.6 90 bottom
RH67  499_0402_1%  [R_0402]  220.75 30.75 90 top
RH70  8.2K_0402_5%  [R_0402]  220.05 50.46 270 bottom
RH73  13_0402_5%  [R_0402]  204.96 51.17 90 top
RH74  10K_0402_5%  [R_0402]  206.02 51.14 90 top
RH75  620_0402_5%  [R_0402]  205.69 48.32 180 top
RH76  10K_0402_5%  [R_0402]  211.96 13.08 90 top
RH77  499_0402_1%  [R_0402]  221.53 32.65 90 top
RH78  4.7K_0201_5%  [R_0201]  220.02 31.47 90 top
RH80  1K_0402_5%  [R_0402]  224.02 29.49 0 top
RH81  1K_0402_5%  [R_0402]  227.55 31.87 180 top
RH83  1K_0402_5%  [R_0402]  215.1 20.94 270 top
RH86  4.7K_0201_5%  [R_0201]  219.72 28.36 270 top
RH90  10K_0402_5%  [R_0402]  224.96 46.62 180 bottom
RH92  1K_0402_5%  [R_0402]  219.72 17.56 0 bottom
RH93  10K_0402_5%  [R_0402]  220.49 18.26 0 top
RH94  8.2K_0402_5%  [R_0402]  220.49 19.21 0 top
RH95  10K_0402_5%  [R_0402]  221.93 25.62 180 bottom
RH97  15_0402_5%  [R_0402]  219.72 21.53 0 top
RH99  22_0402_5%  [R_0402]  213.86 26.96 0 top
RH100  0_0402_5%  [R_0402]  210.34 8.09 180 top
RH101  1K_0402_5%  [R_0402]  210.85 9.23 180 bottom
RH110  10K_0402_5%  [R_0402]  199.59 39.8 270 top
RH123  10K_0201_5%  [R_0201]  224.53 27.44 180 top
RH124  10K_0201_5%  [R_0201]  223.1 25.2 180 top
RH125  10K_0201_5%  [R_0201]  223.1 25.76 180 top
RH126  10K_0201_5%  [R_0201]  224.53 28.02 180 top
RH127  10K_0201_5%  [R_0201]  224.47 28.59 180 top
RH131  10K_0201_5%  [R_0201]  226.21 34.84 90 top
RH132  10K_0402_5%  [R_0402]  205.46 14.77 270 bottom
RH133  10K_0402_5%  [R_0402]  204.57 14.76 270 bottom
RH152  0_0402_5%  [R_0402]  198.7 45.94 180 bottom
RH153  1M_0402_1%  [R_0402]  199.79 46.81 180 bottom
RH154  0_0402_5%  [R_0402]  202.35 46.44 90 bottom
RH155  0_0402_5%  [R_0402]  203.26 46.45 90 bottom
RH156  30_0402_5%  [R_0402]  205.14 47.99 90 bottom
RH161  0_0402_5%  [R_0402]  187.83 40.04 0 bottom
RH166  0_0402_5%  [R_0402]  187.83 40.93 0 bottom
RH167  0_0402_5%  [R_0402]  188.74 43.59 180 bottom
RH168  0_0402_5%  [R_0402]  188.74 44.48 180 bottom
RH169  0_0402_5%  [R_0402]  187.83 41.82 0 bottom
RH170  0_0402_5%  [R_0402]  187.83 42.71 0 bottom
RH171  2.7K_0402_1%  [R_0402]  202.4 44.12 90 top
RH177  0_0402_5%  [R_0402]  232.79 10.06 180 bottom
RH178  4.99_0402_1%  [R_0402]  231.01 10.44 180 bottom
RH179  4.99_0402_1%  [R_0402]  229.26 10.38 180 bottom
RH180  0_0402_5%  [R_0402]  228.35 34.78 0 top
RH181  4.99_0402_1%  [R_0402]  227.99 11.27 180 bottom
RH182  0_0402_5%  [R_0402]  226.6 10.38 180 bottom
RH183  4.99_0402_1%  [R_0402]  225.45 11.27 180 bottom
RH184  4.99_0402_1%  [R_0402]  224.18 10.38 180 bottom
RH185  0_0402_5%  [R_0402]  221.9 11.27 0 bottom
RH187  0_0402_5%  [R_0402]  239.49 26.68 180 bottom
RH192  100_0402_1%  [R_0402]  189.62 37.55 90 bottom
RH193  113_0402_1%  [R_0402]  193.62 46.82 90 bottom
RH198  1M_0402_5%  [R_0402]  213.55 16.43 90 top
RH199  100K_0402_5%  [R_0402]  216.42 48.23 0 bottom
RH200  20K_0402_5%  [R_0402]  213.67 11.59 90 bottom
RH201  20K_0402_5%  [R_0402]  214.47 16.45 90 top
RH203  10K_0402_5%  [R_0402]  227.48 24.92 270 bottom
RH204  10K_0402_5%  [R_0402]  226.55 23.14 0 bottom
RH207  100K_0402_5%  [R_0402]  222.87 33.57 270 bottom
RH214  100K_0402_5%  [R_0402]  224.96 45.73 180 bottom
RH215  0_0402_5%  [R_0402]  217.94 19.63 315 top
RH221  2.2K_0402_5%  [R_0402]  208.83 43.33 45 top
RH222  2.2K_0402_5%  [R_0402]  209.49 42.7 45 top
RH223  2.2K_0402_5%  [R_0402]  210.12 42.06 45 top
RH224  2.2K_0402_5%  [R_0402]  207.67 42.83 180 top
RH225  2.2K_0402_5%  [R_0402]  207.64 43.71 180 top
RH237  0_0402_5%  [R_0402]  209.46 31.34 90 top
RH238  0_0603_5%  [R_0603]  199.65 44.1 180 top
RH239  0_0603_5%  [R_0603]  216.66 36.54 90 top
RH240  0_0402_5%  [R_0402]  187.64 48.4 0 bottom
RH241  0_0603_5%  [R_0603]  199.65 42.83 180 top
RH242  0_0603_5%  [R_0603]  219.13 38.56 180 top
RH243  10K_0402_5%  [R_0402]  221.61 21.78 270 bottom
RH244  0_0402_5%  [R_0402]  233.41 25.04 90 bottom
RH246  0_0402_5%  [R_0402]  207.35 16.86 90 top
RH247  0_0603_5%  [R_0603]  220.5 40.35 180 top
RH250  0_0402_5%  [R_0402]  207.6 23.39 315 top
RH254  0_1206_5%  [R_1206]  188.93 13.69 90 top
RH255  0_0402_5%  [R_0402]  222.73 20.23 180 top
RH256  0_0402_5%  [R_0402]  202.91 19.45 90 top
RH257  0_0402_5%  [R_0402]  204.54 37.38 270 top
RH258  0_0402_5%  [R_0402]  203.65 37.38 270 top
RH259  0_0402_5%  [R_0402]  187.65 49.35 180 bottom
RH260  0_0402_5%  [R_0402]  199.75 35.61 270 top
RH267  10K_0201_5%  [R_0201]  220.13 29.64 270 top
RH268  10K_0201_5%  [R_0201]  220.71 29.65 0 top
RH279  0_1206_5%  [R_1206]  202.84 12.88 90 top
RH286  0_0402_5%  [R_0402]  202.15 37.5 90 top
RH287  0_0402_5%  [R_0402]  204.05 19.45 90 top
RH288  0_0402_5%  [R_0402]  204.94 19.45 90 top
RH289  0_0603_5%  [R_0603]  196.16 17.5 270 bottom
RH290  0_0402_5%  [R_0402]  198.31 20.42 0 top
RH291  0_0402_5%  [R_0402]  215.88 27.97 180 top
RH292  0_0402_5%  [R_0402]  225.54 39.92 270 top
RH293  0_0402_5%  [R_0402]  216.42 33.88 0 top
RH294  0_0402_5%  [R_0402]  208.02 28.59 0 top
RH295  0_0402_5%  [R_0402]  224.65 39.92 270 top
RH296  0_0402_5%  [R_0402]  219.31 34.64 180 top
RH297  0_0402_5%  [R_0402]  216.88 16.4 90 top
RH298  0_0402_5%  [R_0402]  221.52 42.18 90 top
RH299  0_0402_5%  [R_0402]  215.38 39.34 180 top
RH300  0_0402_5%  [R_0402]  210.28 16.85 90 top
RH302  0_0402_5%  [R_0402]  210.28 15.92 270 top
RH303  0_0402_5%  [R_0402]  206.28 16.85 90 top
RH304  0_0402_5%  [R_0402]  215.88 28.86 180 top
RH305  0_0402_5%  [R_0402]  215.56 33.88 180 top
RH306  0_0402_5%  [R_0402]  202.84 16.65 90 top
RH308  100K_0402_5%  [R_0402]  216.35 19.25 270 top
RH309  10K_0402_5%  [R_0402]  215.56 31.91 180 top
RH310  10K_0402_5%  [R_0402]  208.33 12.09 90 bottom
RH311  8.2K_0201_5%  [R_0201]  217.3 29.5 180 top
RH312  51_0402_5%  [R_0402]  207.81 47.71 0 top
RH313  51_0402_5%  [R_0402]  206.23 46.77 270 top
RH314  51_0402_5%  [R_0402]  204.06 51.16 90 bottom
RH315  51_0402_5%  [R_0402]  206.9 51.14 90 bottom
RH316  10K_0402_5%  [R_0402]  207.54 10.68 0 bottom
RH317  10K_0402_5%  [R_0402]  203.98 11.2 90 bottom
RH318  10K_0402_5%  [R_0402]  204.9 12.98 180 bottom
RH319  10K_0402_5%  [R_0402]  224.69 37.74 90 bottom
RH322  10K_0402_5%  [R_0402]  210.11 12.22 90 bottom
RH323  10K_0402_5%  [R_0402]  211.89 12.22 90 bottom
RH324  10K_0402_5%  [R_0402]  207.32 13.86 90 bottom
RH325  10K_0402_5%  [R_0402]  209.26 24.53 315 top
RH326  10K_0402_5%  [R_0402]  211 12.22 90 bottom
RH327  1K_0402_5%  [R_0402]  219.25 26.69 0 bottom
RH328  1K_0402_5%  [R_0402]  221.34 40.04 180 bottom
RH329  150K_0402_5%  [R_0402]  218.92 27.49 90 top
RH330  49.9K_0402_1%  [R_0402]  211.48 10.38 90 top
RH331  4.7K_0402_5%  [R_0402]  224.06 28.7 90 bottom
RH333  2.2K_0402_5%  [R_0402]  218.64 7.95 180 top
RH334  1K_0402_5%  [R_0402]  232.96 10.36 90 top
RH335  20K_0402_5%  [R_0402]  234.11 10.36 90 top
RH339  10K_0402_5%  [R_0402]  217.65 31.21 180 top
RH340  8.2K_0402_1%  [R_0402]  216.51 26.63 180 top
RH344  10K_0402_5%  [R_0402]  208.81 12.06 90 top
RH345  10K_0402_5%  [R_0402]  224.96 44.84 180 bottom
RH348  10K_0402_5%  [R_0402]  206.36 13.84 90 top
RH351  33_0402_5%  [R_0402]  239.65 19.46 180 bottom
RH352  0_0402_5%  [R_0402]  237.3 16.22 270 bottom
RH353  33_0402_5%  [R_0402]  239.65 18.26 270 bottom
RH355  10K_0402_1%  [R_0402]  217.65 30.26 180 top
RH360  49.9K_0402_1%  [R_0402]  210.98 13.12 270 top
RH361  49.9K_0402_1%  [R_0402]  225.92 36.36 270 bottom
RH364  1K_0402_5%  [R_0402]  192.73 46.82 90 bottom
RH365  10K_0402_5%  [R_0402]  194.55 46.81 90 bottom
RH371  10K_0201_5%  [R_0201]  223.95 36.49 270 top
RH372  10K_0201_5%  [R_0201]  223.48 35.03 180 top
RH373  100K_0402_5%  [R_0402]  221.65 36.85 0 bottom
RH374  2.2K_0402_5%  [R_0402]  215.95 7.95 0 top
RH375  100K_0402_5%  [R_0402]  221.46 27.53 90 top
RH376  49.9K_0402_1%  [R_0402]  226.92 34.57 180 bottom
RH377  10K_0402_5%  [R_0402]  207.29 20.87 270 top
RH378  10K_0402_5%  [R_0402]  223.23 37.74 90 bottom
RH379  100_0402_1%  [R_0402]  207.27 26.59 270 top
RH380  10K_0402_5%  [R_0402]  206.36 13.84 90 bottom
RH400  10K_0201_5%  [R_0201]  224.53 36.51 270 top
RH401  10K_0201_5%  [R_0201]  220.91 37.62 0 bottom
RH402  10K_0402_5%  [R_0402]  226.58 24 90 bottom
RH424  10K_0402_5%  [R_0402]  212.43 21.19 270 top
RH431  100K_0402_5%  [R_0402]  199.87 7.66 270 bottom
RH432  499K_0402_1%  [R_0402]  199.87 5.88 270 bottom
RH433  49.9K_0402_1%  [R_0402]  198.93 4.41 180 bottom
RH434  0_0402_5%  [R_0402]  202.62 10.63 180 bottom
RH435  60.4_0402_1%  [R_0402]  203.31 45.15 90 top
RH436  0_0402_5%  [R_0402]  199.53 45.94 0 bottom
RH437  0_0201_1%  [R_0201]  198.92 47.73 0 bottom
RH439  0_0402_5%  [R_0402]  202.62 9.68 180 bottom
RH440  0_0402_5%  [R_0402]  201.72 11.54 0 bottom
RH441  0_0402_5%  [R_0402]  193.26 5.17 0 bottom
RH442  0_0402_5%  [R_0402]  194.37 6.06 180 bottom
RH443  0_0402_5%  [R_0402]  219.26 27.58 0 bottom
RH444  0_0402_5%  [R_0402]  219.27 25.81 0 bottom
RH445  0_0402_5%  [R_0402]  198.93 7.84 180 bottom
RH553  10K_0402_5%  [R_0402]  229.4 33.59 180 bottom
RH554  10K_0402_5%  [R_0402]  230.31 33.59 90 bottom
RH555  10K_0402_5%  [R_0402]  229.38 32.71 180 bottom
RH556  10K_0402_5%  [R_0402]  230.22 32.71 0 bottom
RH600  100K_0402_5%  [R_0402]  227.61 14.63 180 bottom
RH601  100K_0402_5%  [R_0402]  201.07 16.66 90 bottom
RH602  100K_0402_5%  [R_0402]  222.51 21.77 270 bottom
RH603  10K_0402_5%  [R_0402]  214.35 48.23 180 top
RH604  4.7K_0402_5%  [R_0402]  215.5 49.29 90 top
RH605  20K_0402_5%  [R_0402]  217.63 46.71 180 top
RH606  100K_0402_5%  [R_0402]  218.67 46.52 0 top
RH607  100K_0402_5%  [R_0402]  213.15 46.52 0 top
RH608  100K_0402_5%  [R_0402]  212.72 43.81 270 top
RH609  200_0402_1%  [R_0402]  219.5 45.63 180 bottom
RH610  200_0402_1%  [R_0402]  217.64 44.93 180 top
RH611  200_0402_1%  [R_0402]  217.64 45.82 180 top
RH612  150_0402_1%  [R_0402]  220.06 48.09 180 bottom
RH613  20K_0402_5%  [R_0402]  215.84 46.52 180 top
RH614  20K_0402_5%  [R_0402]  216.77 49.29 90 top
RH615  2.2K_0402_5%  [R_0402]  201.07 16.67 90 top
RH616  0_0402_5%  [R_0402]  211.55 47.73 270 top
RH617  75K_0402_5%  [R_0402]  218.78 36.42 0 top
RH618  75K_0402_5%  [R_0402]  226.04 33.69 270 bottom
RH619  0_0402_5%  [R_0402]  142.9 82.49 90 bottom
RH620  0_0402_5%  [R_0402]  142.9 85.19 270 bottom
RH621  75K_0402_5%  [R_0402]  209.72 10.41 0 top
RH622  75K_0402_5%  [R_0402]  234.13 33.22 180 bottom
RH623  0_0402_5%  [R_0402]  233.22 34.11 0 bottom
RH624  0_0402_5%  [R_0402]  233.22 35 0 bottom
RH625  0_0402_5%  [R_0402]  220.63 33.55 0 bottom
RH626  100K_0201_5%  [R_0201]  187.63 45.83 90 top
RH627  100K_0201_5%  [R_0201]  173.43 50.25 0 bottom
RH628  100K_0201_5%  [R_0201]  222.17 23.67 90 top
RH629  100K_0201_5%  [R_0201]  218.64 24.03 0 top
RH630  100K_0201_5%  [R_0201]  183.05 32.18 90 bottom
RH631  100K_0201_5%  [R_0201]  223.5 23.74 90 bottom
RH632  100K_0201_5%  [R_0201]  219.8 23.23 90 top
RH633  75K_0201_5%  [R_0201]  222.8 26.03 270 bottom
RH634  100K_0201_5%  [R_0201]  212.99 14.95 0 bottom
RH635  100K_0201_5%  [R_0201]  233.41 26.72 90 bottom
RH636  100K_0201_5%  [R_0201]  222.27 44.16 180 bottom
RH637  100K_0201_5%  [R_0201]  221.7 42.57 180 bottom
RI13  10K_0402_5%  [R_0402]  341.02 65.88 270 top
RI14  22.1K_0402_1%  [R_0402]  336.85 69.19 270 top
RI27  0_0402_5%  [R_0402]  331.23 52.87 90 top
RI28  0_0402_5%  [R_0402]  332.12 52.86 90 top
RI29  0_0402_5%  [R_0402]  333.13 50.76 90 top
RI30  0_0402_5%  [R_0402]  334.01 50.76 90 top
RI47  0_0402_5%  [R_0402]  325.86 52.92 90 top
RI48  0_0402_5%  [R_0402]  326.72 52.92 90 top
RI49  0_0402_5%  [R_0402]  290.99 38.32 0 bottom
RI50  0_0402_5%  [R_0402]  290.99 37.3 0 bottom
RL1  10K_0402_5%  [R_0402]  316.13 85.18 180 top
RL2  10K_0402_5%  [R_0402]  316.13 83.91 180 top
RL3  0_0402_5%  [R_0402]  329.98 84.8 0 top
RL4  4.7K_0402_5%  [R_0402]  324.9 80.86 270 top
RL5  10K_0402_5%  [R_0402]  326.67 83.28 270 top
RL6  4.7K_0402_5%  [R_0402]  326.04 80.86 0 top
RL7  0_0402_5%  [R_0402]  328.45 82.39 90 top
RL8  0_0603_5%  [R_0603]  315.88 89.12 180 top
RL9  10K_0402_5%  [R_0402]  327.56 83.28 270 top
RL11  1M_0402_5%  [R_0402]  326.55 88.1 90 top
RL12  1K_0402_5%  [R_0402]  316.13 86.45 180 top
RL13  3.01K_0402_1%  [R_0402]  326.55 90.26 0 top
RL14  150_0402_5%  [R_0402]  319.2 113.56 0 top
RL15  75_0402_1%  [R_0402]  327.07 119.25 270 top
RL16  75_0402_1%  [R_0402]  330.07 119.25 270 top
RL17  75_0402_1%  [R_0402]  333.07 119.25 270 top
RL18  75_0402_1%  [R_0402]  336.06 119.25 270 top
RL19  150_0402_5%  [R_0402]  345.26 124.51 180 bottom
RL20  150_0402_5%  [R_0402]  345.26 125.4 180 bottom
RL29  1M_0402_5%  [R_0402]  312.7 88.36 90 top
RL30  1M_0402_5%  [R_0402]  310.93 90.64 0 top
RL34  0_0402_5%  [R_0402]  327.44 88.99 270 top
RL70  10K_0402_5%  [R_0402]  221.4 17.37 180 top
RL71  2.2_0603_5%  [R_0603]  327.94 94.07 90 top
RL72  2.2_0603_5%  [R_0603]  326.67 94.07 90 top
RL73  2.2_0603_5%  [R_0603]  325.28 94.07 90 top
RL74  2.2_0603_5%  [R_0603]  324.01 94.07 90 top
RL75  2.2_0603_5%  [R_0603]  322.61 94.07 90 top
RL76  2.2_0603_5%  [R_0603]  321.34 94.07 90 top
RL77  2.2_0603_5%  [R_0603]  319.82 94.07 90 top
RL78  2.2_0603_5%  [R_0603]  318.55 94.07 90 top
RN1  100K_0402_5%  [R_0402]  266.48 17.49 270 bottom
RN2  100K_0402_5%  [R_0402]  267.42 20.71 270 bottom
RN3  10K_0402_5%  [R_0402]  261.9 17.36 270 bottom
RN4  10K_0402_5%  [R_0402]  264.32 3.9 90 top
RN5  10K_0402_5%  [R_0402]  263.43 4.79 270 top
RN6  4.7K_0402_5%  [R_0402]  249.35 23.47 270 bottom
RN7  4.7K_0402_5%  [R_0402]  249.35 21.18 270 bottom
RN8  4.7K_0402_5%  [R_0402]  248.33 22.55 90 bottom
RN9  4.7K_0402_5%  [R_0402]  248.33 21.18 270 bottom
RN10  4.7K_0402_5%  [R_0402]  249.84 10.63 270 bottom
RN11  4.7K_0402_5%  [R_0402]  249.84 12.03 90 bottom
RN12  4.7K_0402_5%  [R_0402]  247.81 9.74 90 bottom
RN13  4.7K_0402_5%  [R_0402]  247.81 12.03 90 bottom
RN14  4.7K_0402_5%  [R_0402]  247.32 23.47 270 bottom
RN15  7.87K_0402_1%  [R_0402]  247.32 21.18 270 bottom
RN16  4.7K_0402_5%  [R_0402]  250.85 9.74 90 bottom
RN17  4.7K_0402_5%  [R_0402]  250.85 12.03 90 bottom
RN18  4.7K_0402_5%  [R_0402]  253.27 17.74 180 bottom
RN19  4.7K_0402_5%  [R_0402]  252.38 16.85 0 bottom
RN20  4.7K_0402_5%  [R_0402]  248.82 9.74 90 bottom
RN21  4.7K_0402_5%  [R_0402]  248.82 12.92 270 bottom
RN37  10K_0402_5%  [R_0402]  351.31 5.3 90 top
RN99  0_0402_5%  [R_0402]  343.82 9.62 90 top
RN100  0_0402_5%  [R_0402]  362 12.39 90 bottom
RN101  0_0402_5%  [R_0402]  327.83 63.32 90 bottom
RN226  4.7K_0402_5%  [R_0402]  270.42 9.53 90 top
RN227  0_0402_5%  [R_0402]  269.31 11.44 0 top
RPC1  33_0804_8P4R_5%  [RP_0804_8P4R]  233.21 13.42 90 bottom
RPC2  33_0804_8P4R_5%  [RP_0804_8P4R]  234.25 10.12 270 bottom
RPE7  10K_8P4R_5%  [RP_0804_8P4R]  327.18 17.62 180 bottom
RPE9  100K_0804_8P4R_5%  [RP_0804_8P4R]  321.47 24.35 270 top
RPE10  100K_0804_8P4R_5%  [RP_0804_8P4R]  326.26 47.66 0 top
RPE11  100K_0804_8P4R_5%  [RP_0804_8P4R]  310.67 22.82 180 top
RPE12  2.2K_0804_8P4R_5%  [RP_0804_8P4R]  326.24 44.21 0 top
RPH6  10K_0804_8P4R_5%  [RP_0804_8P4R]  198.35 16.16 270 bottom
RPH7  10K_0804_8P4R_5%  [RP_0804_8P4R]  215.86 23.96 0 top
RPH8  15K_0804_8P4R_5%  [RP_0804_8P4R]  199.85 17.56 270 top
RR3  10K_0402_5%  [R_0402]  16.87 73.89 270 top
RR4  6.2K_0402_1%  [R_0402]  13.76 63.73 270 top
RR5  0_0402_5%  [R_0402]  21.93 65.94 0 top
RR6  0_0402_5%  [R_0402]  22.82 68.1 0 top
RR7  0_0402_5%  [R_0402]  22.82 69.06 0 top
RR8  0_0402_5%  [R_0402]  22.82 70.01 0 top
RR9  0_0402_5%  [R_0402]  21.93 64.1 0 top
RR10  0_0402_5%  [R_0402]  21.93 64.99 0 top
RR19  10K_0402_5%  [R_0402]  15.09 72.98 90 top
RT50  3.3K_0402_5%  [R_0402]  49.02 94.39 180 bottom
RT51  3.3K_0402_5%  [R_0402]  50.03 83.77 180 bottom
RT52  3.3K_0402_5%  [R_0402]  46.67 82.74 90 bottom
RT53  3.3K_0402_5%  [R_0402]  45.4 82.74 90 bottom
RT54  0_0402_5%  [R_0402]  30.13 82.89 270 bottom
RT55  0_0402_5%  [R_0402]  32.05 82.91 270 bottom
RT56  0_0402_5%  [R_0402]  31.02 82.89 270 bottom
RT57  0_0402_5%  [R_0402]  28.86 82.89 270 bottom
RT58  0_0402_5%  [R_0402]  17.56 83.53 90 top
RT59  0_0402_5%  [R_0402]  21.11 84.55 270 top
RT60  0_0402_5%  [R_0402]  33.83 81.99 90 bottom
RT63  0_0402_5%  [R_0402]  25.4 88.29 180 bottom
RT64  0_0402_5%  [R_0402]  35.87 83.25 270 bottom
RT65  0_0402_5%  [R_0402]  34.98 83.25 270 bottom
RT66  3.3K_0402_5%  [R_0402]  31.54 84.86 180 top
RT67  3.3K_0402_5%  [R_0402]  31.54 83.97 180 top
RT68  10K_0402_5%  [R_0402]  32.94 82.91 270 bottom
RT69  0_0402_5%  [R_0402]  28.22 84.48 180 bottom
RT70  0_0402_5%  [R_0402]  28.22 85.43 180 bottom
RT71  1M_0402_5%  [R_0402]  40.23 86.13 0 bottom
RT72  0_0402_5%  [R_0402]  37.75 89.88 0 bottom
RT73  0_0402_5%  [R_0402]  37.75 85.82 0 bottom
RT74  0_0402_5%  [R_0402]  40.16 87.85 0 bottom
RT75  0_0402_5%  [R_0402]  37.75 90.77 0 bottom
RT76  10K_0402_1%  [R_0402]  32.05 90.58 180 top
RT81  100K_0402_5%  [R_0402]  25.4 86.26 180 bottom
RT82  1M_0402_5%  [R_0402]  23.41 88.34 90 bottom
RT83  0_0402_5%  [R_0402]  25.4 87.27 180 bottom
RT84  0_0402_5%  [R_0402]  30.64 87.85 180 top
RT85  0_0402_5%  [R_0402]  30.64 88.74 180 top
RT86  1M_0402_5%  [R_0402]  37.75 86.83 0 bottom
RT87  0_0402_5%  [R_0402]  30.53 94.39 270 bottom
RT88  0_0402_5%  [R_0402]  31.42 94.39 270 bottom
RT89  0_0402_5%  [R_0402]  27.8 98.02 270 bottom
RT90  0_0402_5%  [R_0402]  28.69 98.02 270 bottom
RT92  0_0402_5%  [R_0402]  29.11 94.58 270 bottom
RT93  0_0402_5%  [R_0402]  28.22 94.58 270 bottom
RT95  100K_0402_5%  [R_0402]  28.22 90.39 180 bottom
RT96  100K_0402_5%  [R_0402]  28.22 92.55 180 bottom
RT97  0_0402_5%  [R_0402]  41.05 89.75 180 bottom
RT98  0_0402_5%  [R_0402]  37.75 88.86 0 bottom
RT99  0_0402_5%  [R_0402]  40.16 88.86 0 bottom
RT100  15K_0402_0.1%  [R_0402]  25.4 89.31 180 bottom
RT101  100K_0402_5%  [R_0402]  31.92 86 0 top
RT103  0_0402_5%  [R_0402]  38.46 93.12 90 bottom
RT104  0_0402_5%  [R_0402]  36.55 93.12 90 bottom
RT105  0_0402_5%  [R_0402]  37.58 93.12 90 bottom
RT106  10K_0402_5%  [R_0402]  30.65 86.89 180 top
RT107  10K_0402_5%  [R_0402]  31.03 85.88 180 top
RT108  0_0402_5%  [R_0402]  35.61 94.13 90 bottom
RT109  0_0402_5%  [R_0402]  34.72 94.13 90 bottom
RT110  0_0402_5%  [R_0402]  38.66 87.85 180 bottom
RT111  100K_0402_5%  [R_0402]  35.39 101.31 0 bottom
RT120  0_0402_5%  [R_0402]  16.22 112.79 180 bottom
RT121  0_0402_5%  [R_0402]  16.22 113.71 180 bottom
RT122  0_0402_5%  [R_0402]  15.37 111.58 0 top
RT123  0_0402_5%  [R_0402]  15.37 112.5 0 top
RT130  100K_0402_5%  [R_0402]  23.85 106.03 0 bottom
RT131  100K_0402_5%  [R_0402]  22.98 106.03 180 bottom
RT132  0_0402_5%  [R_0402]  20.3 105.38 270 bottom
RT133  0_0402_5%  [R_0402]  19.41 105.38 270 bottom
RT135  4.7K_0402_5%  [R_0402]  26.64 109.56 0 top
RT136  4.7K_0402_5%  [R_0402]  26.64 110.45 0 top
RT137  4.7K_0402_5%  [R_0402]  26.64 108.61 0 top
RT138  4.7K_0402_5%  [R_0402]  25.13 109.68 90 top
RT139  4.7K_0402_5%  [R_0402]  17.64 119.93 270 top
RT140  4.7K_0402_5%  [R_0402]  18.53 119.93 270 top
RT141  4.7K_0402_5%  [R_0402]  23.22 110.78 270 top
RT142  4.7K_0402_5%  [R_0402]  23.22 111.65 90 top
RT246  10K_0402_5%  [R_0402]  21.89 109.74 90 top
RT300  4.99K_0402_1%  [R_0402]  18.78 108.74 180 bottom
RT303  0_0402_5%  [R_0402]  17.62 114.58 0 top
RT304  4.7K_0402_5%  [R_0402]  24.86 106.58 0 top
RT305  4.7K_0402_5%  [R_0402]  25.37 107.66 0 top
RT306  0_0402_5%  [R_0402]  16.75 119.93 270 top
RT307  0_0402_5%  [R_0402]  15.86 119.93 270 top
RT308  4.7K_0402_5%  [R_0402]  27.22 105.8 90 top
RT339  0_0402_5%  [R_0402]  33.75 86.26 90 top
RT375  0_0402_5%  [R_0402]  27.86 96.49 270 top
RT376  0_0402_5%  [R_0402]  26.97 96.49 270 top
RT377  43K_0402_1%  [R_0402]  32.05 91.46 180 top
RT378  10K_0402_5%  [R_0402]  25.4 85.24 180 bottom
RT379  10K_0402_5%  [R_0402]  25.4 84.23 180 bottom
RT380  0_0402_5%  [R_0402]  18.59 108.85 90 top
RT393  100K_0402_5%  [R_0402]  31.15 105.2 180 bottom
RT397  0_0603_5%  [R_0603]  16.38 103.89 90 bottom
RT398  0_0603_5%  [R_0603]  17.59 103.89 90 bottom
RT414  2M_0402_5%  [R_0402]  20.24 106.26 0 bottom
RT415  2M_0402_5%  [R_0402]  19.41 106.26 180 bottom
RT416  220K_0201_5%  [R_0201]  11.62 116.11 270 bottom
RT417  220K_0201_5%  [R_0201]  11.62 116.7 90 bottom
RT418  220K_0201_5%  [R_0201]  11.73 108.4 270 bottom
RT419  220K_0201_5%  [R_0201]  11.73 109.02 90 bottom
RV1  4.7K_0402_5%  [R_0402]  113.19 101.77 270 bottom
RV2  4.7K_0402_5%  [R_0402]  111.66 101.51 270 bottom
RV3  100K_0402_5%  [R_0402]  145.7 108.8 180 bottom
RV4  270K_0402_5%  [R_0402]  126.65 114.39 90 top
RV5  47K_0402_5%  [R_0402]  125.12 111.98 270 top
RV6  47K_0402_5%  [R_0402]  127.46 98.39 0 top
RV7  100K_0402_5%  [R_0402]  111.66 103.72 270 bottom
RV8  10K_0402_5%  [R_0402]  108.36 103.6 270 bottom
RV9  47K_0402_5%  [R_0402]  123.49 99.39 90 top
RV10  470_0402_1%  [R_0402]  101.32 121.89 180 top
